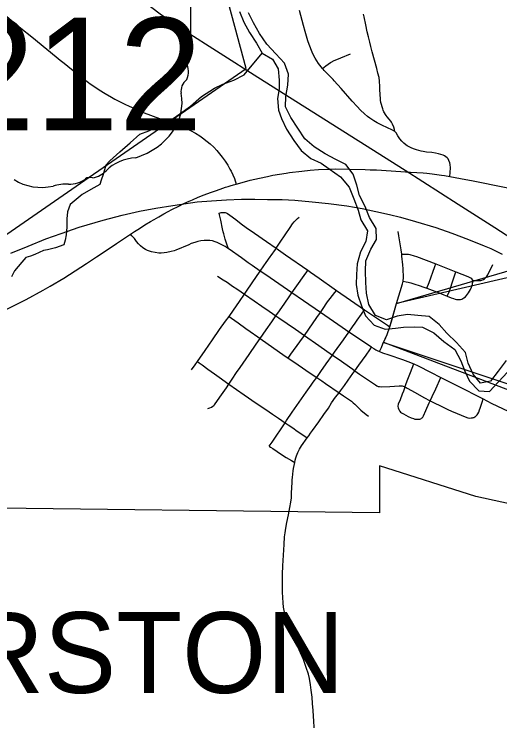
# Model space of a CAD drawing. Extents: x -7.1 to 34, y 0 to 22.
# Drawn here: x 4.741 to 5.309, y 16.818 to 17.646 of the extents above; entities that cross this region are included whole.
import ezdxf

# ---------------------------------------------------------------- set-up
doc = ezdxf.new("R2010")
doc.units = 0
for name, color, linetype in [('GM_X_City_Street', 7, 'Continuous'), ('GM_X_Corporation', 7, 'Continuous'), ('GM_X_Corporation_Text', 7, 'Continuous'), ('GM_X_County_Road', 7, 'Continuous'), ('GM_X_Major_River', 7, 'Continuous'), ('GM_X_Minor_River', 7, 'Continuous'), ('GM_X_Rail_Line', 7, 'Continuous'), ('GM_X_State_Location', 7, 'Continuous'), ('GM_X_State_Route', 7, 'Continuous'), ('GM_X_State_Shield', 7, 'Continuous'), ('SH_Text', 7, 'Continuous')]:
    doc.layers.add(name, color=color, linetype=linetype)

msp = doc.modelspace()

# ---------------------------------------------------------------- linework, layer by layer
at = {"layer": 'GM_X_City_Street'}
for points in [[(5.25087, 17.45573), (5.25139, 17.46029), (5.25166, 17.46586), (5.25142, 17.4697), (5.25093, 17.47175), (5.24987, 17.47432), (5.24887, 17.47612), (5.2478, 17.47736), (5.24634, 17.47873), (5.24474, 17.47974), (5.24302, 17.48056), (5.24047, 17.48155), (5.23765, 17.48229), (5.23408, 17.48296), (5.23, 17.48356), (5.22352, 17.48427), (5.21952, 17.48489), (5.21753, 17.48529), (5.21205, 17.48675), (5.20972, 17.48756), (5.20643, 17.48886), (5.20318, 17.49041), (5.20104, 17.49165), (5.19949, 17.49274), (5.19688, 17.49472), (5.19471, 17.49707), (5.19232, 17.49983), (5.19, 17.50331), (5.18802, 17.50657), (5.18648, 17.50835), (5.18372, 17.5099), (5.1816, 17.51086), (5.17949, 17.51183), (5.16971, 17.51659), (5.16599, 17.51849), (5.16193, 17.52077), (5.15738, 17.52383), (5.15461, 17.52581), (5.15097, 17.52886), (5.14634, 17.53332), (5.14232, 17.53745), (5.13664, 17.54374), (5.12386, 17.55855), (5.11565, 17.5678), (5.11416, 17.56935), (5.10369, 17.57983), (5.10257, 17.58115), (5.10167, 17.58223), (5.09878, 17.58586), (5.09699, 17.58809), (5.09333, 17.59426), (5.09135, 17.59774), (5.08961, 17.60124), (5.08614, 17.61005), (5.0848, 17.61458), (5.08152, 17.62549), (5.07966, 17.63243), (5.07507, 17.65014)], [(5.18648, 17.50835), (5.18617, 17.51064), (5.18547, 17.51319), (5.18397, 17.517), (5.18266, 17.51938), (5.18201, 17.52033), (5.17992, 17.52284), (5.17744, 17.52555), (5.17648, 17.52687), (5.17366, 17.53141), (5.17283, 17.53322), (5.17234, 17.53488), (5.17033, 17.5424), (5.16982, 17.54492), (5.16958, 17.5465), (5.16903, 17.55725), (5.16892, 17.56084), (5.16844, 17.56705), (5.168, 17.57155), (5.16681, 17.57643), (5.16539, 17.58191), (5.1627, 17.59201), (5.16017, 17.60139), (5.15857, 17.60794), (5.15722, 17.61292), (5.15559, 17.61897), (5.15418, 17.62501), (5.15244, 17.63331), (5.15054, 17.64244), (5.14974, 17.64581)], [(5.10167, 17.58223), (5.10583, 17.58527), (5.11107, 17.58894), (5.11205, 17.58951), (5.11568, 17.59129), (5.12059, 17.59346), (5.1234, 17.59467), (5.13456, 17.59907)], [(4.98096, 17.41284), (4.98333, 17.41326), (4.98623, 17.41353), (4.98793, 17.41333), (4.98927, 17.41291), (4.99057, 17.41226), (4.99331, 17.41043), (5.00025, 17.40535), (5.00673, 17.40025), (5.01242, 17.39602), (5.02242, 17.38913), (5.03627, 17.37958), (5.04771, 17.3715), (5.05854, 17.36393), (5.08468, 17.34573), (5.08762, 17.34367), (5.09811, 17.33638), (5.11537, 17.32411), (5.11835, 17.32205), (5.13449, 17.31087), (5.15109, 17.29953), (5.16526, 17.29015), (5.1781, 17.28142), (5.18071, 17.27964)], [(4.99173, 17.37107), (4.98994, 17.37644), (4.98804, 17.38239), (4.98617, 17.38838), (4.98547, 17.39087), (4.98477, 17.39429), (4.98275, 17.40444), (4.98143, 17.41085), (4.98096, 17.41284)], [(4.94867, 17.22925), (4.95279, 17.23519), (4.95535, 17.23891), (4.96435, 17.25184), (4.97307, 17.26438), (4.98139, 17.27626), (4.98837, 17.28608), (4.99244, 17.29178), (4.99752, 17.29894), (5.00461, 17.30912), (5.01062, 17.3179), (5.01276, 17.32124), (5.01951, 17.33113), (5.02895, 17.34478), (5.03316, 17.35087), (5.03597, 17.35494), (5.04065, 17.36158), (5.04187, 17.36324), (5.04676, 17.37016), (5.04771, 17.3715), (5.05247, 17.37864), (5.06388, 17.39593), (5.06686, 17.40017), (5.06871, 17.40256), (5.07024, 17.40396), (5.07277, 17.4063), (5.07454, 17.4079)], [(5.16857, 17.25071), (5.17074, 17.2554), (5.17268, 17.25946), (5.17477, 17.26422), (5.1774, 17.27052), (5.18071, 17.27964), (5.18219, 17.28478), (5.18248, 17.28578), (5.18865, 17.30671), (5.19553, 17.33001), (5.19591, 17.33147), (5.19638, 17.33316), (5.19682, 17.33731), (5.19628, 17.34748), (5.19587, 17.35211), (5.19482, 17.36228), (5.19462, 17.36466), (5.19388, 17.36967), (5.19114, 17.3863), (5.19032, 17.39106)], [(5.19462, 17.36466), (5.19862, 17.3648), (5.20272, 17.3646), (5.20416, 17.36434), (5.20925, 17.36286), (5.21195, 17.3619), (5.23448, 17.35321), (5.25798, 17.34395), (5.27198, 17.3385), (5.27451, 17.33729), (5.27587, 17.33649), (5.27682, 17.33557), (5.27734, 17.33465), (5.27763, 17.33385)], [(4.96779, 17.18402), (4.97001, 17.18481), (4.97188, 17.18568), (4.97354, 17.18681), (4.9746, 17.18763), (4.9754, 17.18839), (4.98165, 17.19713), (4.98929, 17.20814), (4.99227, 17.2125), (4.99614, 17.21827), (5.00122, 17.226), (5.00556, 17.23213), (5.01581, 17.24705), (5.02428, 17.25913), (5.02903, 17.26597), (5.03607, 17.27612), (5.04246, 17.28532), (5.04736, 17.29236), (5.05138, 17.29848), (5.0576, 17.30735), (5.06265, 17.31481), (5.06609, 17.31947), (5.07175, 17.32755), (5.0802, 17.33975), (5.08334, 17.34396), (5.08468, 17.34573)], [(5.22416, 17.32487), (5.22659, 17.33147), (5.2334, 17.35018), (5.23448, 17.35321)], [(5.26338, 17.31149), (5.26512, 17.31204), (5.26619, 17.31257), (5.2675, 17.31334), (5.2692, 17.31476), (5.2705, 17.31622), (5.2727, 17.31949), (5.27497, 17.32318), (5.27643, 17.32603), (5.27716, 17.32809), (5.27742, 17.32923), (5.27762, 17.3308), (5.27773, 17.33193), (5.27763, 17.33385), (5.28734, 17.33393), (5.28854, 17.33419), (5.29015, 17.33481), (5.29149, 17.33566), (5.2924, 17.33654), (5.29384, 17.33819), (5.2953, 17.34039), (5.2967, 17.34306), (5.30034, 17.3507), (5.30118, 17.35248)], [(4.97912, 17.33905), (4.98567, 17.33469), (4.99018, 17.33167), (4.99656, 17.32729), (5.00159, 17.3239), (5.00662, 17.32045), (5.01062, 17.3179), (5.02183, 17.31015), (5.03085, 17.30376), (5.03959, 17.29781), (5.04736, 17.29236), (5.05083, 17.29004), (5.07014, 17.27671), (5.08061, 17.26929), (5.09755, 17.25751), (5.11349, 17.24648), (5.12028, 17.24197), (5.1373, 17.23002), (5.13987, 17.22821), (5.14518, 17.22421), (5.15467, 17.21773), (5.16385, 17.21146), (5.16541, 17.21047), (5.16701, 17.20978), (5.16872, 17.20952), (5.17077, 17.20938), (5.18084, 17.20983), (5.19157, 17.21051), (5.19439, 17.21041), (5.19521, 17.21029), (5.19643, 17.21001), (5.19856, 17.20921), (5.20094, 17.2079), (5.21032, 17.20264), (5.22058, 17.19688), (5.22798, 17.19298), (5.24461, 17.18486), (5.24866, 17.18292), (5.25299, 17.18098), (5.27086, 17.17343), (5.27204, 17.1731), (5.27375, 17.1728), (5.27606, 17.17283), (5.2774, 17.17307), (5.27815, 17.1733)], [(5.24785, 17.31545), (5.2506, 17.3212), (5.25539, 17.3358), (5.25725, 17.34153), (5.25798, 17.34395)], [(5.19638, 17.33316), (5.19985, 17.33243), (5.20207, 17.332), (5.20535, 17.33108), (5.21001, 17.32961), (5.21512, 17.328), (5.2205, 17.32609), (5.22416, 17.32487), (5.23645, 17.32019), (5.24395, 17.31706), (5.24785, 17.31545), (5.25245, 17.31366), (5.25519, 17.31264), (5.25719, 17.31196), (5.25875, 17.31164), (5.26048, 17.3114), (5.26338, 17.31149)], [(5.06165, 17.24292), (5.06484, 17.24748), (5.07539, 17.262), (5.08061, 17.26929), (5.08588, 17.27693), (5.09531, 17.29052), (5.09939, 17.29639), (5.10168, 17.29978), (5.10778, 17.30873), (5.11082, 17.31286), (5.11625, 17.3196), (5.11835, 17.32205)], [(5.03957, 17.13989), (5.04277, 17.14444), (5.05806, 17.16726), (5.05975, 17.16971), (5.06617, 17.17969), (5.07453, 17.19154), (5.08265, 17.20309), (5.08855, 17.21121), (5.09096, 17.21464), (5.09513, 17.22029), (5.09972, 17.22708), (5.10633, 17.23642), (5.11349, 17.24648), (5.11588, 17.24987), (5.12628, 17.26435), (5.13263, 17.27336), (5.13711, 17.27973), (5.13999, 17.28383), (5.14245, 17.28733), (5.14734, 17.29429), (5.15109, 17.29953)], [(4.99244, 17.29178), (4.99551, 17.28971), (5.00309, 17.2843), (5.01227, 17.27771), (5.01732, 17.27412), (5.02614, 17.26789), (5.02903, 17.26597), (5.03168, 17.26404), (5.0555, 17.24707), (5.06165, 17.24292), (5.06696, 17.23945), (5.07334, 17.23504), (5.08739, 17.22549), (5.09513, 17.22029), (5.10093, 17.21635), (5.10547, 17.21318), (5.12118, 17.2022)], [(5.15906, 17.2557), (5.16181, 17.25413), (5.16419, 17.2528), (5.16579, 17.25202), (5.16857, 17.25071), (5.17203, 17.2493), (5.17969, 17.24666), (5.19534, 17.24146), (5.20183, 17.23903), (5.20885, 17.23616), (5.21371, 17.23383), (5.22847, 17.22636), (5.24058, 17.22022), (5.25904, 17.21102), (5.28977, 17.19506)], [(4.95535, 17.23891), (4.95745, 17.23741), (4.96089, 17.23495), (4.96771, 17.23007), (4.97534, 17.22461), (4.98371, 17.21863), (4.9894, 17.21455), (4.99227, 17.2125), (5.01021, 17.2001), (5.02434, 17.19033), (5.03551, 17.18285), (5.0435, 17.17733), (5.05019, 17.1727), (5.05806, 17.16726), (5.06178, 17.16469), (5.06696, 17.16111), (5.07208, 17.15756), (5.07753, 17.15379), (5.08387, 17.14941)], [(5.19693, 17.20478), (5.19856, 17.20921), (5.19915, 17.21092), (5.19997, 17.21331), (5.20172, 17.21825), (5.20479, 17.22624), (5.20885, 17.23616)], [(5.21682, 17.17184), (5.21789, 17.17253), (5.21871, 17.17317), (5.21936, 17.17392), (5.22006, 17.1754), (5.22266, 17.18152), (5.22685, 17.19054), (5.22798, 17.19298), (5.23038, 17.19802), (5.23446, 17.20699), (5.24058, 17.22022)], [(5.12118, 17.2022), (5.12642, 17.19874), (5.13444, 17.19349), (5.13598, 17.19234), (5.1379, 17.19074), (5.13968, 17.18906), (5.14045, 17.18822), (5.14594, 17.18263), (5.14673, 17.18202), (5.15283, 17.1771), (5.15559, 17.17507)], [(5.1909, 17.18385), (5.19074, 17.18469), (5.19055, 17.18633), (5.19087, 17.18922), (5.19301, 17.19465), (5.19562, 17.20124), (5.19693, 17.20478)], [(5.27815, 17.1733), (5.27885, 17.1735), (5.28001, 17.17405), (5.28102, 17.17468), (5.28216, 17.17563), (5.28281, 17.17652), (5.28353, 17.1775), (5.28479, 17.17983), (5.28575, 17.1822), (5.2864, 17.1842), (5.2888, 17.1915), (5.28977, 17.19506)], [(5.1909, 17.18385), (5.19127, 17.18274), (5.19191, 17.18137), (5.19244, 17.18067), (5.19332, 17.17979), (5.19447, 17.17898), (5.19651, 17.17764), (5.20226, 17.17448), (5.2055, 17.17307), (5.20839, 17.17204), (5.20986, 17.17162), (5.21139, 17.1714), (5.21312, 17.17129), (5.21482, 17.17139), (5.21584, 17.17155), (5.21682, 17.17184)], [(5.03957, 17.13989), (5.04106, 17.13867), (5.04357, 17.1369), (5.04859, 17.13343), (5.05282, 17.13076), (5.05944, 17.12648), (5.06544, 17.1232), (5.06949, 17.12084)]]:
    msp.add_lwpolyline(points, dxfattribs=at)
at = {"layer": 'GM_X_Corporation'}
for points in [[(4.66078, 17.33891), (5.01248, 17.58202), (4.95822, 17.78352)], [(5.44979, 17.77553), (5.44491, 17.49815), (5.46735, 17.4319), (5.54835, 17.4335), (5.57094, 17.43541), (5.58061, 17.43882), (5.58942, 17.44491), (5.60882, 17.46611), (5.65893, 17.5405), (5.66045, 17.46228), (5.66031, 17.26124), (5.51991, 17.26134), (5.51906, 17.23325), (5.49778, 17.22989), (5.49442, 17.08659), (5.4945, 17.06168), (5.46984, 17.02308), (5.40648, 17.05363), (5.28118, 17.08093), (5.16844, 17.11693), (5.16845, 17.06178), (4.6588, 17.06783)]]:
    msp.add_lwpolyline(points, dxfattribs=at)
at = {"layer": 'GM_X_County_Road'}
msp.add_line((5.28977, 17.19506), (5.29429, 17.19286), dxfattribs=at)
for points in [[(4.98793, 17.37348), (4.98021, 17.37758), (4.97844, 17.37836), (4.97601, 17.37928), (4.97297, 17.3801), (4.97001, 17.38057), (4.96666, 17.38075), (4.96348, 17.38057), (4.95954, 17.38017), (4.95579, 17.37943), (4.95221, 17.37841), (4.94812, 17.37695), (4.94527, 17.37575), (4.93028, 17.36936), (4.92834, 17.36872), (4.92483, 17.36772), (4.91977, 17.36659), (4.91657, 17.36608), (4.91285, 17.36585), (4.91014, 17.36594), (4.90606, 17.36641), (4.90184, 17.36725), (4.89921, 17.36803), (4.89714, 17.3689), (4.89463, 17.37017), (4.89162, 17.37209), (4.8886, 17.37448), (4.88655, 17.37677), (4.88429, 17.37945), (4.88165, 17.3828), (4.87879, 17.38627), (4.87725, 17.38809)], [(5.15906, 17.2557), (5.13263, 17.27336), (5.12474, 17.27879), (5.09939, 17.29639), (5.07965, 17.31007), (5.06609, 17.31947), (5.04049, 17.33703), (5.03451, 17.34105), (5.02895, 17.34478), (5.01934, 17.35149), (5.0149, 17.35469), (5.00696, 17.3603), (4.99245, 17.37063), (4.99173, 17.37107), (4.98922, 17.37273), (4.98793, 17.37348)], [(5.06671, 17.10331), (5.06763, 17.11091), (5.06809, 17.11353), (5.06949, 17.12084), (5.06998, 17.12333), (5.07065, 17.12603), (5.07142, 17.1287), (5.07289, 17.13256), (5.07495, 17.13644), (5.07736, 17.14027), (5.08387, 17.14941), (5.08575, 17.15208), (5.08788, 17.15521), (5.0901, 17.15824), (5.09766, 17.16821), (5.10354, 17.17699), (5.10871, 17.18449), (5.11253, 17.19052), (5.11723, 17.19708), (5.12118, 17.2022), (5.12294, 17.2045), (5.1275, 17.21077), (5.13209, 17.21723), (5.13747, 17.22483), (5.13987, 17.22821), (5.14437, 17.23455), (5.15303, 17.24656), (5.1571, 17.25257), (5.15906, 17.2557)], [(5.29429, 17.19286), (5.30027, 17.18992), (5.31916, 17.18069), (5.32886, 17.17595), (5.34068, 17.17023), (5.34769, 17.16677), (5.35886, 17.16124), (5.36985, 17.15581), (5.37071, 17.15539)], [(5.05512, 16.98894), (5.05513, 16.98991), (5.05544, 16.99976), (5.05684, 17.02449), (5.05751, 17.03367), (5.05798, 17.03836), (5.05885, 17.04389), (5.0601, 17.05034), (5.06206, 17.05932), (5.06375, 17.06809), (5.06483, 17.07441), (5.06545, 17.07948), (5.06575, 17.08471), (5.06632, 17.0977), (5.06643, 17.09941)], [(5.06643, 17.09941), (5.06652, 17.10059), (5.06671, 17.10331)], [(5.09286, 16.7982), (5.09087, 16.83043), (5.0903, 16.83866), (5.08964, 16.84574), (5.08874, 16.85414), (5.08796, 16.86032), (5.08659, 16.86763), (5.08536, 16.87273), (5.08291, 16.88083), (5.08135, 16.88552), (5.07951, 16.89006), (5.069, 16.91363), (5.0646, 16.92399), (5.06204, 16.93066), (5.05929, 16.93943), (5.05744, 16.94527), (5.05636, 16.95143), (5.05575, 16.95651), (5.05529, 16.96267), (5.05498, 16.96867), (5.05512, 16.98894)]]:
    msp.add_lwpolyline(points, dxfattribs=at)
at = {"layer": 'GM_X_Major_River'}
for points in [[(5.00461, 17.64894), (5.00969, 17.63648), (5.0163, 17.62404), (5.02442, 17.61161), (5.0314, 17.59993), (5.04325, 17.59286), (5.04985, 17.58156), (5.05114, 17.56829), (5.05126, 17.55842), (5.04912, 17.54701), (5.05042, 17.53337), (5.05396, 17.52354), (5.05981, 17.51109), (5.06832, 17.49791), (5.07682, 17.48587), (5.08832, 17.47652), (5.10016, 17.47135), (5.10973, 17.46464), (5.12276, 17.45531), (5.13315, 17.44329), (5.13864, 17.42932), (5.14373, 17.4161), (5.14691, 17.40475), (5.15466, 17.39194), (5.15253, 17.37939), (5.14622, 17.36755), (5.14259, 17.35347), (5.1416, 17.34093), (5.14136, 17.32917), (5.14341, 17.31667), (5.14736, 17.30419), (5.15206, 17.29249), (5.16244, 17.28161), (5.17503, 17.27683), (5.18717, 17.27811), (5.19665, 17.27899), (5.20956, 17.27952), (5.21905, 17.27925), (5.23204, 17.27258), (5.24394, 17.26248), (5.25696, 17.25315), (5.26396, 17.23957), (5.26866, 17.22749), (5.27412, 17.21579), (5.28489, 17.20454), (5.29743, 17.20393), (5.30793, 17.21506), (5.31842, 17.22657)], [(5.31674, 17.24021), (5.3074, 17.22757), (5.29842, 17.21608), (5.28668, 17.21367), (5.2782, 17.22419), (5.27235, 17.23702), (5.26916, 17.2495), (5.25876, 17.26114), (5.24724, 17.27201), (5.23838, 17.28215), (5.22688, 17.29149), (5.21357, 17.29285), (5.20141, 17.29384), (5.18928, 17.29218), (5.1768, 17.28785), (5.16382, 17.29301), (5.15607, 17.30582), (5.15326, 17.31906), (5.15273, 17.33158), (5.15219, 17.34486), (5.15242, 17.357), (5.15833, 17.37036), (5.16503, 17.38182), (5.1645, 17.39472), (5.15675, 17.40753), (5.15166, 17.42037), (5.14505, 17.43319), (5.14224, 17.4453), (5.13791, 17.45815), (5.12904, 17.46981), (5.11758, 17.47536), (5.10496, 17.48204), (5.09196, 17.49023), (5.08121, 17.49958), (5.07309, 17.51201), (5.06496, 17.52482), (5.05873, 17.53726), (5.05897, 17.54941), (5.06108, 17.56272), (5.06207, 17.57525), (5.05736, 17.58848), (5.04735, 17.59936), (5.03659, 17.61062), (5.02808, 17.62304), (5.0211, 17.63548), (5.01526, 17.64717)]]:
    msp.add_lwpolyline(points, dxfattribs=at)
at = {"layer": 'GM_X_Minor_River'}
for points in [[(4.8483, 17.46881), (4.85291, 17.47405), (4.86455, 17.48443), (4.87658, 17.49483), (4.88785, 17.50521), (4.89843, 17.50913), (4.90863, 17.51419), (4.92185, 17.52004), (4.93503, 17.52893), (4.94746, 17.53781), (4.96023, 17.54935), (4.97531, 17.55902), (4.98512, 17.56369), (4.99798, 17.5684), (5.01005, 17.57462), (5.0314, 17.59993)], [(4.8483, 17.46881), (4.84504, 17.4581), (4.84287, 17.45121), (4.84104, 17.44623), (4.83053, 17.44036), (4.82039, 17.4345), (4.80654, 17.42286), (4.80326, 17.41405), (4.80262, 17.40605), (4.80238, 17.39614), (4.80175, 17.38737), (4.80071, 17.38088), (4.79889, 17.37552), (4.7891, 17.37195), (4.78004, 17.36991), (4.77513, 17.36907), (4.76497, 17.36435), (4.76008, 17.36237), (4.75442, 17.36076), (4.74996, 17.35536), (4.7414, 17.34495), (4.73771, 17.33804)]]:
    msp.add_lwpolyline(points, dxfattribs=at)
at = {"layer": 'GM_X_Rail_Line'}
for points in [[(4.77968, 17.78409), (4.78866, 17.77019), (4.80843, 17.74447), (4.82791, 17.72139), (4.84985, 17.69851), (4.87245, 17.67723), (4.89249, 17.66096), (4.91179, 17.64621), (4.93808, 17.62825), (5.02602, 17.57207), (5.19851, 17.46313), (5.26054, 17.42304), (5.30348, 17.39599), (5.34206, 17.37084), (5.37289, 17.34947), (5.42301, 17.30978), (5.47332, 17.2706), (5.50244, 17.24942)], [(4.73684, 17.36564), (4.75717, 17.37405), (4.77807, 17.38247), (4.79594, 17.3889), (4.81684, 17.39609), (4.84502, 17.4046), (4.86715, 17.41027), (4.88748, 17.41481), (4.90668, 17.41869), (4.92663, 17.42171), (4.95529, 17.42578), (4.97202, 17.4271), (4.98952, 17.42824), (5.00711, 17.42909), (5.02252, 17.42919), (5.03764, 17.42878), (5.05449, 17.42852), (5.06952, 17.42777), (5.08957, 17.42606), (5.10886, 17.42398), (5.13042, 17.42115), (5.14829, 17.41803), (5.16437, 17.41462), (5.18026, 17.41122), (5.19331, 17.40791), (5.21071, 17.40309), (5.23444, 17.3959), (5.25345, 17.38928), (5.27293, 17.382), (5.29128, 17.37424), (5.29875, 17.37112), (5.31227, 17.36479)]]:
    msp.add_lwpolyline(points, dxfattribs=at)
at = {"layer": 'GM_X_State_Route'}
for p, q in [((4.79761, 17.58975), (4.81827, 17.57316)), ((4.82778, 17.56585), (4.83003, 17.56429))]:
    msp.add_line(p, q, dxfattribs=at)
for points in [[(4.70413, 17.66621), (4.72151, 17.6519), (4.73742, 17.63883), (4.74876, 17.62941)], [(4.74876, 17.62941), (4.76142, 17.61897), (4.79682, 17.59039), (4.79761, 17.58975)], [(4.81827, 17.57316), (4.82342, 17.56919), (4.82778, 17.56585)], [(4.83003, 17.56429), (4.83427, 17.56136), (4.84033, 17.55724), (4.84755, 17.55269), (4.85497, 17.54836), (4.85875, 17.54623), (4.87114, 17.53991), (4.8748, 17.53828), (4.89318, 17.53023), (4.91117, 17.52368), (4.92574, 17.51831)], [(4.92574, 17.51831), (4.92897, 17.51716), (4.93664, 17.51418), (4.9433, 17.51128), (4.9473, 17.50945), (4.95319, 17.50618), (4.95819, 17.50303), (4.96129, 17.5009), (4.96695, 17.49659), (4.97018, 17.49386), (4.9745, 17.48979), (4.97796, 17.48595), (4.98128, 17.48211), (4.98431, 17.47837), (4.98776, 17.47365), (4.99088, 17.46871), (4.99351, 17.46409), (4.99488, 17.46168), (4.99872, 17.45316), (5.00074, 17.44665)], [(4.97317, 17.43761), (4.97785, 17.43927), (4.98512, 17.44175), (4.98841, 17.44292), (4.99127, 17.44395), (4.99377, 17.44469), (4.99773, 17.44576), (5.00074, 17.44665), (5.01331, 17.45013), (5.01723, 17.45112), (5.02817, 17.45358), (5.03748, 17.45567), (5.04388, 17.45697), (5.05923, 17.45969), (5.06323, 17.46025), (5.07764, 17.462), (5.08749, 17.46294), (5.09718, 17.46363), (5.11038, 17.46422), (5.11742, 17.46446), (5.13313, 17.46437)], [(5.13313, 17.46437), (5.15167, 17.46384), (5.15773, 17.46358), (5.16516, 17.46323), (5.20502, 17.46084), (5.2198, 17.45971), (5.22383, 17.45935), (5.23036, 17.45869), (5.24116, 17.45732), (5.24477, 17.45675), (5.25087, 17.45573), (5.2696, 17.45222), (5.27618, 17.45088), (5.31696, 17.44253), (5.31887, 17.4422)], [(4.86086, 17.37712), (4.87725, 17.38809), (4.88185, 17.39105), (4.88756, 17.3948), (4.89374, 17.39885), (4.90068, 17.40304), (4.90476, 17.40526), (4.91044, 17.40855), (4.91595, 17.41184), (4.9213, 17.41472), (4.92562, 17.41695), (4.93349, 17.4209), (4.93887, 17.42349), (4.94391, 17.42585), (4.94969, 17.42844), (4.95627, 17.43123), (4.9635, 17.43402), (4.97091, 17.43681), (4.97317, 17.43761)], [(4.66873, 17.27306), (4.67818, 17.27677), (4.68162, 17.27813), (4.68388, 17.27904), (4.71624, 17.2927), (4.72244, 17.29553), (4.74648, 17.3072), (4.7551, 17.31165), (4.77495, 17.32246), (4.78323, 17.32729), (4.79893, 17.33672), (4.81225, 17.34509), (4.82553, 17.35356), (4.83729, 17.36136), (4.84858, 17.3689), (4.86086, 17.37712)]]:
    msp.add_lwpolyline(points, dxfattribs=at)
at = {"layer": 'GM_X_State_Shield'}
for p, q in [((4.94779, 17.59931), (4.94779, 17.70399)), ((4.94775, 17.59933), (4.94779, 17.59931))]:
    msp.add_line(p, q, dxfattribs=at)
for centre, major_axis, start_param, end_param in [((4.94694, 17.59162), (0.00568, 0), 1.883978, 3.671073), ((4.94387, 17.5989), (0.00393, 0), 5.05454, 6.418171), ((4.91082, 17.57839), (0.03409, 0), 5.934695, 6.695948), ((4.96093, 17.5555), (0.0248, 0), 2.387724, 3.262537), ((4.84996, 17.54218), (0.08742, 0), 5.101752, 6.440018), ((4.88683, 17.43929), (0.04788, 0), 1.647645, 2.488434), ((4.82616, 17.47607), (0.02824, 0), 4.937069, 5.64225), ((4.82937, 17.44856), (0.00752, 0), 1.147584, 2.315152), ((4.7726, 17.48293), (0.05011, 0), 4.026481, 4.996735), ((4.80155, 17.41374), (0.04118, 0), 1.495662, 1.94098), ((4.80522, 17.46794), (0.0267, 0), 4.691044, 5.507374)]:
    msp.add_ellipse(centre, major_axis=major_axis, ratio=0.8, start_param=start_param, end_param=end_param, dxfattribs=at)
at = {"layer": 'SH_Text'}
for points in [[(5.18865, 17.30671), (9.36522, 18.52859), (9.36522, 18.27657)], [(5.17351, 17.26139), (9.32617, 15.87658), (9.32612, 15.67668)]]:
    msp.add_lwpolyline(points, close=True, dxfattribs=at)
msp.add_lwpolyline([(5.17268, 17.25946), (5.1774, 17.27052), (5.18071, 17.27964), (5.18865, 17.30671)], dxfattribs=at)

# ---------------------------------------------------------------- texts
at = {"layer": 'GM_X_Corporation_Text'}
msp.add_text('BOWERSTON', height=0.094697, rotation=0.00001, dxfattribs=at).set_placement((4.29737, 16.85083))
at = {"layer": 'GM_X_State_Location'}
for s, p in [('s', (4.77929, 17.58222)), ('r', (4.77928, 17.58222))]:
    msp.add_text(s, height=0.000189, dxfattribs=at).set_placement(p)
at = {"layer": 'GM_X_State_Shield'}
msp.add_text('212', height=0.131836, dxfattribs=at).set_placement((4.6672, 17.50958))

doc.saveas('drawing.dxf')
